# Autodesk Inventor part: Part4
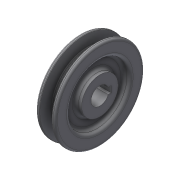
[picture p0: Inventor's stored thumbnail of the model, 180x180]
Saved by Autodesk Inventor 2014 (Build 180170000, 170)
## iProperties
Created: 2018-12
Part Number: Part4
Material: Generic
Document SubType Name: Modeling
Designer: hi
Density: 1 g/cm^3
Appearance: Default
Author: hi
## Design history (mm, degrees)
sketch "Sketch1"
  geometry: L1 (-9.5, -42.7)-(9.5, 42.7); L2 (9.5, -42.7)-(-9.5, 42.7); L3 (-24.538, 0)-(24.305, 0); L4 (-9.5, 8.5)-(9.5, 8.5); L5 (3.194, 34.391)-(5.781, 42.355); L6 (-3.194, 34.391)-(-5.781, 42.355); L7 (7.5, 42.7)-(6.257, 42.7); L8 (-6.257, 42.7)-(-7.5, 42.7); L9 (-2.243, 33.7)-(2.243, 33.7); L10 (9.5, 8.5)-(9.5, 17.5); L11 (9.5, 32)-(9.5, 40.7); L12 (-9.5, 40.7)-(-9.5, 32); L13 (-9.5, 17.5)-(-9.5, 8.5); L14 (-9.5, 17.5)-(-6.5, 17.5); L15 (6.5, 17.5)-(9.5, 17.5); L16 (-6.5, 29)-(-6.5, 29); L17 (6.5, 29)-(6.5, 29); L18 (3.5, 26)-(3.5, 20.5); L19 (-3.5, 26)-(-3.5, 20.5); A1 r 3 centre (-6.5, 32) between (-9.5, 32) and (-6.5, 29); A2 r 3 centre (-6.5, 26) between (-3.5, 26) and (-6.5, 29); A3 r 3 centre (6.5, 26) between (6.5, 29) and (3.5, 26); A4 r 3 centre (6.5, 32) between (6.5, 29) and (9.5, 32); A5 r 3 centre (6.5, 20.5) between (3.5, 20.5) and (6.5, 17.5); A6 r 3 centre (-6.5, 20.5) between (-6.5, 17.5) and (-3.5, 20.5); A7 r 2 centre (-7.5, 40.7) between (-7.5, 42.7) and (-9.5, 40.7); A8 r 2 centre (7.5, 40.7) between (9.5, 40.7) and (7.5, 42.7); A9 r 1 centre (-2.243, 34.7) between (-3.194, 34.391) and (-2.243, 33.7); A10 r 1 centre (2.243, 34.7) between (2.243, 33.7) and (3.194, 34.391); A11 r 0.5 centre (-6.257, 42.2) between (-5.781, 42.355) and (-6.257, 42.7); A12 r 0.5 centre (6.257, 42.2) between (6.257, 42.7) and (5.781, 42.355); 3 further points
  constraints: 38 end point, 24 point on circle, 24 tangent, 12 centre point, 8 equal radius, 7 parallel, 4 perpendicular, 4 point on line, 2 midpoint
  dimensions: "d4" = 17 diameter of L4 L3; "d7" = 36 deg angle of L5 L6; "d12" = 3 radius of A1; "d13" = 2 radius of A7; "d14" = 1 radius of A9; "d15" = 0.5 radius of A11
revolve "Revolution1" sketch "Sketch1" stored, may be unused: angle "d16" = 90 deg
sketch "Sketch2"
  geometry: L1 (-3, 10.8)-(3, 10.8); L2 (-3, 10.8)-(-3, 7.953); L3 (3, 10.8)-(3, 7.953); C1 r 17.5 at (0, 0) reference; A1 r 8.5 centre (0, 0) between (3, 7.953) and (-3, 7.953)
  constraints: 6 end point, 2 point on circle, 1 centre point, 1 coincident
extrude "Extrusion1" cut sketch "Sketch2" stored distance "d20" = 10; taper "d21" = 0 deg
body "Solid1"
other parameters: "d0" = 19, "d2" = 85.4, "d3" = 67.4, "d8" = 58, "d9" = 35, "d10" = 3.5, "d11" = 3.5
